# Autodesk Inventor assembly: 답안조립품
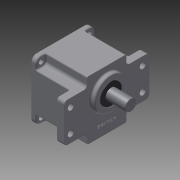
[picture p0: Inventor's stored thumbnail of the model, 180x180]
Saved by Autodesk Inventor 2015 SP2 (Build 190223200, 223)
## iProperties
Created: 2015-06
Part Number: 답안조립품
Document SubType Name: Assembly
Designer: AMC
Author: AMC
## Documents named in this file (12)
- C:\Users\AMC\Desktop\450620V1020\답안조립품.iam
- C:\Users\AMC\Desktop\450620V1020\본체.ipt
- C:\Users\AMC\Desktop\450620V1020\커버.ipt
- C:\Users\AMC\Desktop\450620V1020\오일실 8x22x7.ipt
- C:\Users\AMC\Desktop\450620V1020\오일실 17x32x8.ipt
- C:\Users\AMC\Desktop\450620V1020\베어링 6003.ipt
- 베어링 6003.ipt
- C:\Users\AMC\Desktop\450620V1020\베어링 608.ipt
- 베어링 608.ipt
- C:\Users\AMC\Desktop\450620V1020\서브축.ipt
- C:\Users\AMC\Desktop\450620V1020\메인축.ipt
- C:\Users\AMC\Desktop\450620V1020\M4x0.5x16.ipt
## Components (4 placed, 1 different names)
1. M4x0.5x12:1
2. M4x0.5x12:2
3. M4x0.5x12:3
4. M4x0.5x12:4
